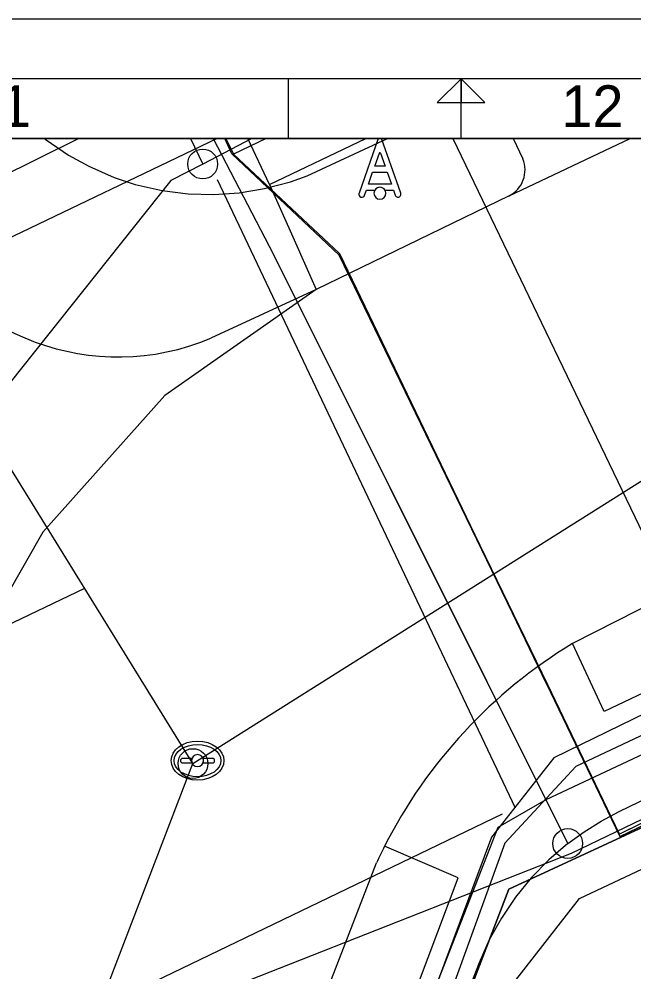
# Model space of a CAD drawing. Extents: x 192672 to 192910, y 446344 to 446512.
# Drawn here: x 192776.14 to 192786.44, y 446495.79 to 446511.76 of the extents above; entities that cross this region are included whole.
import ezdxf

# ---------------------------------------------------------------- set-up
doc = ezdxf.new("R2010")
doc.units = 0
for name, color, linetype in [('1010 viewport', 7, 'Continuous'), ('B-OI-KL-()_OVERIG_RIOOLVRIJVERVAL-S', 7, 'Continuous'), ('B-OI-KL-BUISLEIDING_OLIEGASCHEMICALIEN_GASLAGEDRUK-G', 7, 'Continuous'), ('B-OI-KL-DATA-G', 7, 'Continuous'), ('B-OI-KL-DATA_GTWP-S', 7, 'Continuous'), ('B-OI-KL-DATA_KABELBED-G', 7, 'Continuous'), ('B-OI-KL-DATA_MANTELBUIS-G', 7, 'Continuous'), ('B-OI-KL-ET_LS-G', 7, 'Continuous'), ('B-OI-KL-GAS_LD_TSTUK-S', 7, 'Continuous'), ('B-OI-KL-WATER-G', 7, 'Continuous'), ('B-OI-RI-RIOOLVRIJVERVAL-G', 7, 'Continuous'), ('bovenleidingmast', 7, 'Continuous'), ('Default', 7, 'Continuous'), ('inspectie-   rioolput', 7, 'Continuous'), ('kant open verharding', 7, 'Continuous'), ('kant verharding', 7, 'Continuous'), ('verkeerseiland - berm', 7, 'Continuous'), ('X-XX-AL-TEKENBLAD-S', 7, 'Continuous')]:
    doc.layers.add(name, color=color, linetype=linetype)

# ---------------------------------------------------------------- blocks, each defined once
blk = doc.blocks.new('B-OI-KL-GAS_LD_TSTUK-S')
at = {"layer": 'Default'}
blk.add_circle((0, 0), 0.25, dxfattribs=at)
blk = doc.blocks.new('B-OI-KL-()_OVERIG_RIOOLVRIJVERVAL-S')
at = {"layer": 'Default'}
blk.add_circle((0, 0), 0.25, dxfattribs=at)
blk = doc.blocks.new('B-OI-KL-DATA_GTWP-S')
at = {"layer": 'Default'}
blk.add_circle((0, 0), 0.25, dxfattribs=at)

msp = doc.modelspace()

# ---------------------------------------------------------------- linework, layer by layer
at = {"layer": '1010 viewport'}
msp.add_lwpolyline([(192675.743, 446509.756), (192860.643, 446509.756), (192860.643, 446345.556), (192675.743, 446345.556)], close=True, dxfattribs=at)
at = {"layer": 'B-OI-KL-BUISLEIDING_OLIEGASCHEMICALIEN_GASLAGEDRUK-G'}
for p in [(192779.009, 446509.756), (192780.039, 446509.756)]:
    msp.add_line(p, (192779.213, 446509.327), dxfattribs=at)
for points in [[(192808.99, 446509.756), (192805.748, 446508.276), (192801.187, 446506.24), (192794.261, 446502.995), (192789.059, 446500.595), (192784.967, 446498.672), (192784.158, 446498.207), (192778.689, 446484.216), (192775.51, 446475.031), (192756.472, 446424.494), (192754.598, 446419.974), (192751.089, 446410.462)], [(192779.213, 446509.327), (192778.681, 446509.051), (192774.928, 446504.345), (192770.865, 446499.368), (192770.261, 446499.113)], [(192779.453, 446509.069), (192784.45, 446498.54)], [(192772.219, 446493.35), (192773.033, 446493.045), (192784.238, 446498.438)]]:
    msp.add_lwpolyline(points, dxfattribs=at)
at = {"layer": 'B-OI-KL-DATA-G'}
for p in [(192779.601, 446509.756), (192780.278, 446509.756)]:
    msp.add_line(p, (192779.727, 446509.493), dxfattribs=at)
for points in [[(192745.236, 446436.264), (192745.276, 446436.371), (192749.491, 446434.791), (192749.794, 446435.599), (192768.74, 446486.807), (192770.369, 446486.306), (192778.924, 446483.081), (192784.343, 446497.176), (192794.941, 446502.078), (192811.396, 446509.756)], [(192757.844, 446425.655), (192756.715, 446426.08), (192759.12, 446432.478), (192750.822, 446435.215), (192749.794, 446435.599), (192768.74, 446486.807), (192770.369, 446486.306), (192778.924, 446483.081), (192784.343, 446497.176), (192794.941, 446502.078), (192811.396, 446509.756)], [(192757.844, 446425.655), (192756.715, 446426.08), (192759.12, 446432.478), (192750.822, 446435.215), (192749.794, 446435.599), (192768.74, 446486.807), (192770.369, 446486.306), (192778.924, 446483.081), (192784.343, 446497.176), (192794.941, 446502.078), (192811.396, 446509.756)], [(192757.844, 446425.655), (192756.715, 446426.08), (192759.12, 446432.478), (192750.822, 446435.215), (192749.794, 446435.599), (192768.74, 446486.807), (192770.369, 446486.306), (192778.924, 446483.081), (192784.343, 446497.176), (192794.941, 446502.078), (192811.396, 446509.756)], [(192757.844, 446425.655), (192756.715, 446426.08), (192759.12, 446432.478), (192750.822, 446435.215), (192749.794, 446435.599), (192768.74, 446486.807), (192770.369, 446486.306), (192778.924, 446483.081), (192784.343, 446497.176), (192794.941, 446502.078), (192811.396, 446509.756)], [(192757.844, 446425.655), (192756.715, 446426.08), (192759.12, 446432.478), (192750.822, 446435.215), (192749.794, 446435.599), (192768.74, 446486.807), (192770.369, 446486.306), (192778.924, 446483.081), (192784.343, 446497.176), (192794.941, 446502.078), (192811.396, 446509.756)], [(192757.844, 446425.655), (192756.715, 446426.08), (192759.12, 446432.478), (192750.822, 446435.215), (192749.794, 446435.599), (192768.74, 446486.807), (192770.369, 446486.306), (192778.924, 446483.081), (192784.343, 446497.176), (192794.941, 446502.078), (192811.396, 446509.756)], [(192757.844, 446425.655), (192756.715, 446426.08), (192759.12, 446432.478), (192750.822, 446435.215), (192749.794, 446435.599), (192768.74, 446486.807), (192770.369, 446486.306), (192778.924, 446483.081), (192784.343, 446497.176), (192794.941, 446502.078), (192811.396, 446509.756)], [(192764.304, 446509.756), (192770.565, 446496.734), (192770.867, 446495.7), (192770.986, 446494.71), (192770.973, 446493.522), (192770.841, 446492.782), (192768.74, 446486.807), (192770.369, 446486.306), (192778.924, 446483.081), (192784.343, 446497.176), (192794.941, 446502.078), (192809.504, 446508.873), (192809.089, 446509.756)], [(192764.304, 446509.756), (192770.565, 446496.734), (192770.867, 446495.7), (192770.986, 446494.71), (192770.973, 446493.522), (192770.841, 446492.782), (192768.74, 446486.807), (192770.369, 446486.306), (192778.924, 446483.081), (192784.343, 446497.176), (192794.941, 446502.078), (192809.504, 446508.873), (192809.089, 446509.756)], [(192768.74, 446486.807), (192770.369, 446486.306), (192778.924, 446483.081), (192784.343, 446497.176), (192794.941, 446502.078), (192811.396, 446509.756)], [(192809.87, 446509.756), (192801.3, 446505.5), (192786.2, 446498.1), (192785, 446500.6), (192781.5, 446507.8), (192779.7, 446509.5), (192779.582, 446509.756)], [(192809.883, 446509.756), (192786.2, 446498.1), (192781.5, 446507.8), (192779.7, 446509.5), (192779.582, 446509.756)], [(192809.883, 446509.756), (192786.2, 446498.1), (192781.5, 446507.8), (192779.7, 446509.5), (192779.582, 446509.756)], [(192779.601, 446509.756), (192779.727, 446509.493), (192781.507, 446507.825), (192784.974, 446500.615), (192786.203, 446498.061), (192789.931, 446499.854), (192801.292, 446505.317), (192810.12, 446509.756)], [(192779.601, 446509.756), (192779.727, 446509.493), (192781.507, 446507.825), (192784.974, 446500.615), (192786.203, 446498.061), (192789.931, 446499.854), (192801.292, 446505.317), (192810.12, 446509.756)], [(192779.727, 446509.493), (192781.507, 446507.825), (192784.974, 446500.615), (192786.203, 446498.061), (192789.931, 446499.854), (192801.292, 446505.317), (192810.12, 446509.756)], [(192768.74, 446486.807), (192770.369, 446486.306), (192778.924, 446483.081), (192784.343, 446497.176), (192794.941, 446502.078), (192809.266, 446508.761), (192809.501, 446508.269)], [(192809.501, 446508.269), (192809.266, 446508.761), (192794.941, 446502.078), (192784.343, 446497.176), (192778.924, 446483.081), (192778.438, 446481.788), (192779.283, 446481.47)], [(192784.723, 446488.03), (192781.328, 446489.335), (192784.343, 446497.176), (192794.941, 446502.078), (192809.266, 446508.761), (192809.501, 446508.269)]]:
    msp.add_lwpolyline(points, dxfattribs=at)
at = {"layer": 'B-OI-KL-DATA_KABELBED-G'}
for points in [[(192779.391, 446509.756), (192780.399, 446507.811), (192784.301, 446500), (192785.331, 446497.94)], [(192785.331, 446497.94), (192785.605, 446498.139), (192785.892, 446498.318), (192786.191, 446498.476), (192789.352, 446500), (192789.594, 446500.117), (192795.704, 446503.063), (192797.607, 446503.981), (192801.113, 446505.672), (192809.291, 446509.756)], [(192780.399, 446507.811), (192783.974, 446500.654)], [(192781.328, 446489.335), (192784.343, 446497.176), (192787.381, 446498.581)], [(192785.331, 446497.94), (192785.012, 446497.666), (192784.719, 446497.366), (192784.454, 446497.04), (192784.219, 446496.692), (192784.015, 446496.325), (192783.845, 446495.941), (192782.051, 446491.343), (192782.051, 446491.343)]]:
    msp.add_lwpolyline(points, dxfattribs=at)
at = {"layer": 'B-OI-KL-DATA_MANTELBUIS-G'}
for points in [[(192784.974, 446500.615), (192781.507, 446507.825)], [(192780.399, 446507.811), (192783.974, 446500.654)]]:
    msp.add_lwpolyline(points, dxfattribs=at)
at = {"layer": 'B-OI-KL-ET_LS-G'}
for points in [[(192807.795, 446509.756), (192785.465, 446499.231), (192784.279, 446497.948), (192782.198, 446492.212), (192772.784, 446495.238), (192772.082, 446495.48), (192769.274, 446501.433)], [(192810.223, 446509.756), (192801.246, 446505.403), (192785.389, 446497.771), (192774.175, 446493.36)], [(192776.559, 446509.756), (192776.59, 446509.73), (192776.962, 446509.476), (192777.302, 446509.288), (192777.728, 446509.102), (192778.082, 446508.986), (192778.536, 446508.882), (192778.968, 446508.828), (192779.402, 446508.816), (192779.822, 446508.844), (192780.25, 446508.914), (192780.686, 446509.03), (192780.964, 446509.13), (192782.312, 446509.756)], [(192790.564, 446503.228), (192790.567, 446502.921), (192790.865, 446502.188), (192785.098, 446499.379), (192784.052, 446498.05), (192776.999, 446479.133), (192776.611, 446479.298), (192776.274, 446479.242)]]:
    msp.add_lwpolyline(points, dxfattribs=at)
at = {"layer": 'B-OI-KL-WATER-G'}
for p, q in [((192779.457, 446509.756), (192767.46, 446504.003)), ((192783.407, 446509.756), (192790.1, 446495.821))]:
    msp.add_line(p, q, dxfattribs=at)
at = {"layer": 'B-OI-RI-RIOOLVRIJVERVAL-G'}
for q in [(192772.573, 446509.756), (192795.666, 446509.756)]:
    msp.add_line((192779.05, 446499.28), q, dxfattribs=at)
for points in [[(192777.234, 446502.213), (192770.738, 446499.109), (192767.197, 446498.456)], [(192759.86, 446449.26), (192779.05, 446499.28)]]:
    msp.add_lwpolyline(points, dxfattribs=at)
at = {"layer": 'bovenleidingmast'}
for points in [[(192782.533, 446508.838), (192782.212, 446509.756), (192782.154, 446509.756), (192781.833, 446508.838)], [(192782.192, 446509.508), (192782.27, 446509.288), (192782.096, 446509.288), (192782.174, 446509.508)], [(192781.927, 446508.805), (192781.956, 446508.888), (192782.096, 446508.888)], [(192782.27, 446508.888), (192782.41, 446508.888), (192782.439, 446508.805)]]:
    msp.add_lwpolyline(points, dxfattribs=at)
msp.add_lwpolyline([(192782.305, 446509.188), (192782.375, 446508.988), (192781.991, 446508.988), (192782.061, 446509.188)], close=True, dxfattribs=at)
for centre, radius, start, end in [((192782.183, 446509.505), 0.01, 19.29, 160.71), ((192781.88, 446508.821), 0.05, 160.71, 340.71), ((192782.183, 446508.838), 0.1, 0, 180), ((192782.183, 446508.838), 0.1, 180, 0), ((192782.183, 446508.838), 0.1, 30, 150), ((192782.486, 446508.821), 0.05, 199.29, 19.29)]:
    msp.add_arc(centre, radius, start, end, dxfattribs=at)
at = {"layer": 'inspectie-   rioolput'}
for p, q in [((192779.033, 446499.367), (192778.876, 446499.367)), ((192779.376, 446499.367), (192779.219, 446499.367)), ((192778.876, 446499.292), (192779.033, 446499.292)), ((192779.219, 446499.292), (192779.376, 446499.292))]:
    msp.add_line(p, q, dxfattribs=at)
for centre, radius, start, end in [((192778.876, 446499.33), 0.0375, 90, 270), ((192779.126, 446499.33), 0.1, 0, 180), ((192779.126, 446499.33), 0.1, 157.9757, 180), ((192779.126, 446499.33), 0.1, 0, 22.0243), ((192779.376, 446499.33), 0.0375, 270, 90), ((192779.126, 446499.33), 0.1, 180, 202.0243), ((192779.126, 446499.33), 0.1, 180, 0), ((192779.126, 446499.33), 0.1, 337.9757, 0)]:
    msp.add_arc(centre, radius, start, end, dxfattribs=at)
for major_axis, ratio in [((-0.442, 0), 0.73911), ((-0.392, 0), 0.689655)]:
    msp.add_ellipse((192779.126, 446499.33), major_axis=major_axis, ratio=ratio, dxfattribs=at)
at = {"layer": 'kant open verharding'}
msp.add_line((192780.331, 446508.982), (192779.967, 446509.756), dxfattribs=at)
for points in [[(192779.53, 446482.124), (192780.051, 446483.746), (192784.415, 446495.597), (192785.528, 446497.018), (192791.864, 446500), (192801.451, 446504.762), (192802.996, 446505.531), (192810.052, 446508.944)], [(192781.115, 446507.223), (192778.58, 446505.448), (192776.532, 446503.157), (192774.342, 446499.324), (192773.367, 446497.097)]]:
    msp.add_lwpolyline(points, dxfattribs=at)
for centre, radius, start, end in [((192777.798, 446510.118), 4.023, 206.7487, 292.6943), ((192789.771, 446494.09), 8.418, 121.1838, 153.1361)]:
    msp.add_arc(centre, radius, start, end, dxfattribs=at)
at = {"layer": 'kant verharding'}
for p, q in [((192784.351, 446508.796), (192786.378, 446509.756)), ((192781.115, 446507.223), (192779.35, 446506.406))]:
    msp.add_line(p, q, dxfattribs=at)
at = {"layer": 'verkeerseiland - berm'}
for p, q in [((192777.138, 446509.756), (192774.205, 446508.307)), ((192780.331, 446508.982), (192781.945, 446509.756)), ((192784.417, 446509.756), (192784.578, 446509.413)), ((192784.351, 446508.796), (192781.115, 446507.223)), ((192779.096, 446489.802), (192782.127, 446497.618))]:
    msp.add_line(p, q, dxfattribs=at)
for points in [[(192780.331, 446508.982), (192780.745, 446508.054), (192781.115, 446507.223)], [(192792.545, 446504.728), (192793.101, 446503.55), (192785.941, 446500.151), (192785.412, 446501.292)], [(192792.545, 446504.728), (192786.498, 446501.848), (192785.412, 446501.292)], [(192780.204, 446488.916), (192780.3, 446488.879), (192783.494, 446497.368), (192782.261, 446497.894)]]:
    msp.add_lwpolyline(points, dxfattribs=at)
for centre, radius, start, end in [((192784.136, 446509.225), 0.48, 296.6196, 22.9823), ((192793.96, 446492.044), 13.08, 153.4311, 154.7751)]:
    msp.add_arc(centre, radius, start, end, dxfattribs=at)
at = {"layer": 'X-XX-AL-TEKENBLAD-S'}
for p, q in [((192909.543, 446511.756), (192671.743, 446511.756)), ((192908.543, 446510.756), (192674.743, 446510.756)), ((192780.643, 446510.756), (192780.643, 446509.756)), ((192783.543, 446509.756), (192783.543, 446510.756))]:
    msp.add_line(p, q, dxfattribs=at)
for points in [[(192783.543, 446510.356), (192783.543, 446510.756), (192783.143, 446510.356), (192783.543, 446510.356)], [(192783.543, 446510.756), (192783.543, 446510.356), (192783.943, 446510.356), (192783.543, 446510.756)]]:
    msp.add_lwpolyline(points, dxfattribs=at)
msp.add_lwpolyline([(192675.743, 446345.556), (192907.543, 446345.556), (192907.543, 446509.756), (192675.743, 446509.756)], close=True, dxfattribs=at)

# ---------------------------------------------------------------- block references
at = {"layer": 'B-OI-KL-()_OVERIG_RIOOLVRIJVERVAL-S'}
msp.add_blockref('B-OI-KL-()_OVERIG_RIOOLVRIJVERVAL-S', (192779.05, 446499.28), dxfattribs=at)
at = {"layer": 'B-OI-KL-DATA_GTWP-S'}
msp.add_blockref('B-OI-KL-DATA_GTWP-S', (192785.331, 446497.94), dxfattribs=at)
msp.add_blockref('B-OI-KL-DATA_GTWP-S', (192785.331, 446497.94), dxfattribs=at)
msp.add_blockref('B-OI-KL-DATA_GTWP-S', (192785.331, 446497.94), dxfattribs=at)
at = {"layer": 'B-OI-KL-GAS_LD_TSTUK-S'}
msp.add_blockref('B-OI-KL-GAS_LD_TSTUK-S', (192779.213, 446509.327), dxfattribs=at)

# ---------------------------------------------------------------- texts
at = {"layer": 'X-XX-AL-TEKENBLAD-S'}
for s, p in [('11', (192775.293, 446509.945)), ('12', (192785.224, 446509.945))]:
    msp.add_text(s, height=0.7, dxfattribs=at).set_placement(p)

doc.saveas('drawing.dxf')
